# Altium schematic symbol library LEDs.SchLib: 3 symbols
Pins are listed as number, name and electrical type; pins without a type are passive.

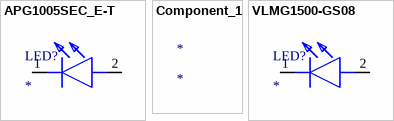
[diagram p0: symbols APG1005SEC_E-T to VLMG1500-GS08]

## APG1005SEC_E-T
designator LED?
LED; Manufacturer_Name: Kingbright; Manufacturer_Part_Number: APG1005SEC/E-T; Description: Standard LEDs - SMD 1.0X0.5MM ULTRA THIN 624nm RED SMD LED
footprint APG1005SECET
pins: 1 K, 2 A

## Component_1
designator *

## VLMG1500-GS08
designator LED?
LED; Manufacturer_Name: Vishay; Manufacturer_Part_Number: VLMG1500-GS08; Description: VISHAY - VLMG1500-GS08.. - LED
footprint LEDC1005X35N
pins: 1 K, 2 A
